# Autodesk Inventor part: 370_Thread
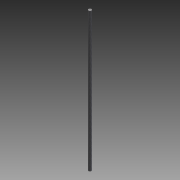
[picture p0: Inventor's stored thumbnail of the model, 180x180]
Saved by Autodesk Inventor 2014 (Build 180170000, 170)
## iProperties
Created: 2013-12
Part Number: 370_Thread
Material: Iron, Malleable
Document SubType Name: Modeling
Designer: Bram
Density: 7.1 g/cm^3
Appearance: Semi-Polished
Author: Bram
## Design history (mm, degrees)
sketch "Sketch1"
  geometry: C1 r 4 at (0, 0); 1 further point
  constraints: 1 centre point, 1 coincident
  dimensions: "d0" = 8 diameter of C1
extrude "Extrusion1" new body sketch "Sketch1" distance "d1" = 370; taper "d2" = 0 deg
thread "Thread1" dims "d3" = 10, "d4" = 0
body "Solid1"
